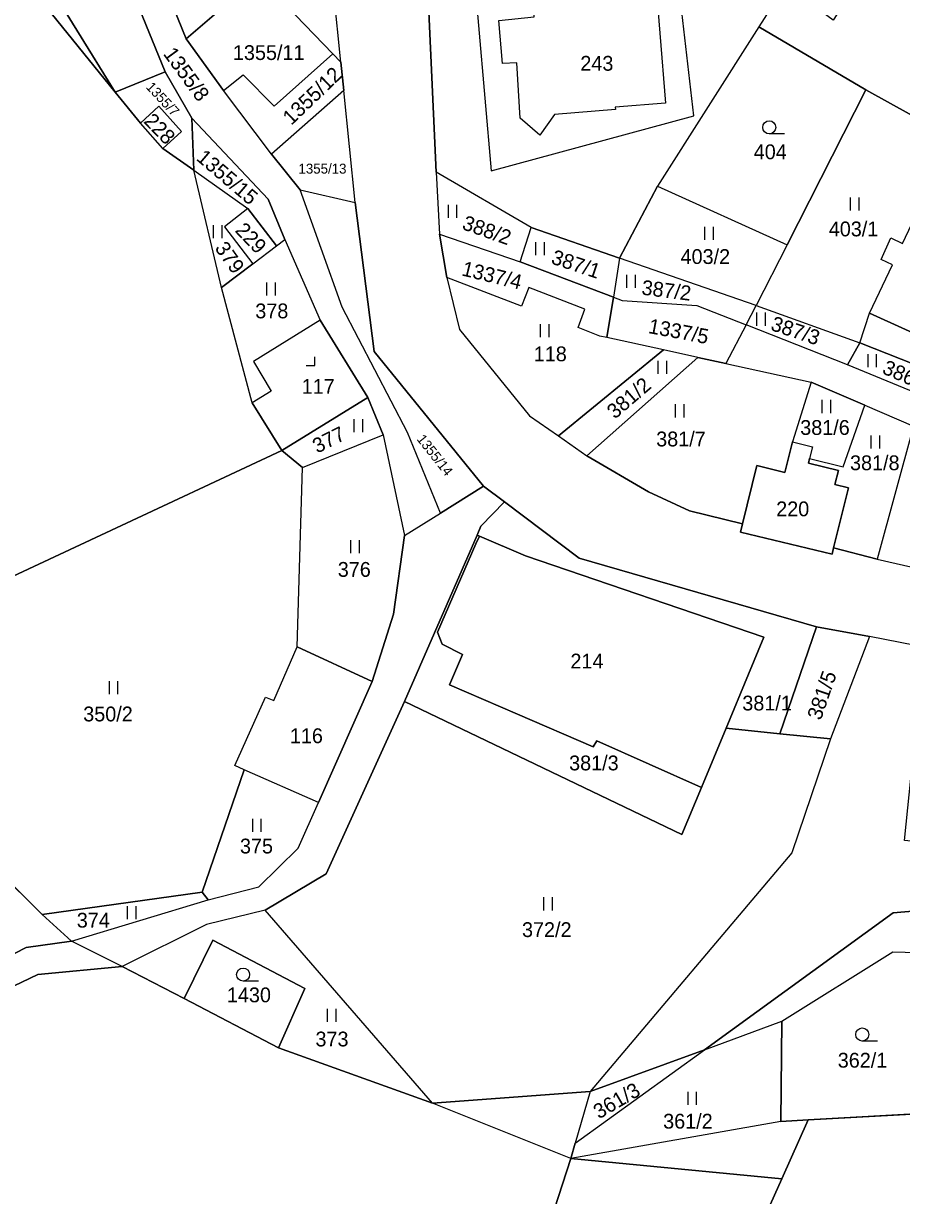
# Model space of a CAD drawing. Extents: x -588699 to -585793, y -1060280 to -1056731.
# Drawn here: x -587382.9 to -587282, y -1058613.5 to -1058478.9 of the extents above; entities that cross this region are included whole.
import ezdxf

# ---------------------------------------------------------------- set-up
doc = ezdxf.new("R2010")
doc.units = 0
for name, color, linetype in [('Druh pozemku', 7, 'Continuous'), ('Lesy', 7, 'Continuous'), ('Parcela nároku', 7, 'Continuous')]:
    doc.layers.add(name, color=color, linetype=linetype)

msp = doc.modelspace()

# ---------------------------------------------------------------- linework, layer by layer
at = {"layer": 'Druh pozemku'}
for p, q in [((-587295.46, -1058491.61), (-587297.21, -1058491.61)), ((-587287.9, -1058498.91), (-587287.9, -1058500.41)), ((-587286.88, -1058500.41), (-587286.88, -1058498.91)), ((-587334.09, -1058499.74), (-587334.09, -1058501.24)), ((-587333.07, -1058501.24), (-587333.07, -1058499.74)), ((-587361.05, -1058502.07), (-587361.05, -1058503.57)), ((-587360.03, -1058503.57), (-587360.03, -1058502.07)), ((-587304.64, -1058502.27), (-587304.64, -1058503.77)), ((-587303.61, -1058503.77), (-587303.61, -1058502.27)), ((-587324.04, -1058504.02), (-587324.04, -1058505.52)), ((-587323.02, -1058505.52), (-587323.02, -1058504.02)), ((-587354.93, -1058508.66), (-587354.93, -1058510.16)), ((-587353.91, -1058510.16), (-587353.91, -1058508.66)), ((-587313.61, -1058507.77), (-587313.61, -1058509.27)), ((-587312.58, -1058509.27), (-587312.58, -1058507.77)), ((-587298.67, -1058512.13), (-587298.67, -1058513.63)), ((-587297.65, -1058513.63), (-587297.65, -1058512.13)), ((-587323.5, -1058513.46), (-587323.5, -1058514.96)), ((-587322.47, -1058514.96), (-587322.47, -1058513.46)), ((-587310.01, -1058517.66), (-587310.01, -1058519.16)), ((-587308.98, -1058519.16), (-587308.98, -1058517.66)), ((-587285.9, -1058516.9), (-587285.9, -1058518.4)), ((-587284.88, -1058518.4), (-587284.88, -1058516.9)), ((-587291.15, -1058522.15), (-587291.15, -1058523.65)), ((-587290.12, -1058523.65), (-587290.12, -1058522.15)), ((-587308.02, -1058522.65), (-587308.02, -1058524.15)), ((-587306.99, -1058524.15), (-587306.99, -1058522.65)), ((-587344.9, -1058524.34), (-587344.9, -1058525.84)), ((-587343.88, -1058525.84), (-587343.88, -1058524.34)), ((-587285.53, -1058526.23), (-587285.53, -1058527.73)), ((-587284.51, -1058527.73), (-587284.51, -1058526.23)), ((-587345.3, -1058538.23), (-587345.3, -1058539.73)), ((-587344.28, -1058539.73), (-587344.28, -1058538.23)), ((-587373.03, -1058554.41), (-587373.03, -1058555.91)), ((-587372.01, -1058555.91), (-587372.01, -1058554.41)), ((-587356.56, -1058570.21), (-587356.56, -1058571.71)), ((-587355.54, -1058571.71), (-587355.54, -1058570.21)), ((-587323.12, -1058579.23), (-587323.12, -1058580.73)), ((-587322.09, -1058580.73), (-587322.09, -1058579.23)), ((-587370.94, -1058580.25), (-587370.94, -1058581.75)), ((-587369.92, -1058581.75), (-587369.92, -1058580.25)), ((-587355.88, -1058588.85), (-587357.63, -1058588.85)), ((-587347.96, -1058592.02), (-587347.96, -1058593.52)), ((-587346.94, -1058593.52), (-587346.94, -1058592.02)), ((-587284.77, -1058595.73), (-587286.52, -1058595.73)), ((-587306.57, -1058601.54), (-587306.57, -1058603.04)), ((-587305.55, -1058603.04), (-587305.55, -1058601.54))]:
    msp.add_line(p, q, dxfattribs=at)
msp.add_lwpolyline([(-587350.4, -1058518.2), (-587349.4, -1058518.2), (-587349.4, -1058517.2)], dxfattribs=at)
for centre in [(-587297.21, -1058490.86), (-587357.63, -1058588.1), (-587286.52, -1058594.98)]:
    msp.add_circle(centre, 0.75, dxfattribs=at)
at = {"layer": 'Lesy'}
for p, q in [((-587380.72, -1058581.19), (-587388.41, -1058573.59)), ((-587377.32, -1058584.26), (-587380.72, -1058581.19)), ((-587371.51, -1058587.16), (-587377.32, -1058584.26)), ((-587371.51, -1058587.16), (-587371.51, -1058587.16)), ((-587277.34, -1058603.93), (-587292.72, -1058604.78))]:
    msp.add_line(p, q, dxfattribs=at)
for points in [[(-587353.56, -1058596.5), (-587364.41, -1058590.86), (-587371.51, -1058587.16)], [(-587292.72, -1058604.78), (-587295.88, -1058604.95), (-587319.99, -1058609.19), (-587335.88, -1058602.84), (-587353.56, -1058596.5)]]:
    msp.add_lwpolyline(points, dxfattribs=at)
at = {"layer": 'Parcela nároku'}
for points in [[(-587366.84, -1058493.28), (-587369.43, -1058490.39), (-587372.32, -1058486.82), (-587383.27, -1058473.29), (-587387.17, -1058457.65), (-587399.19, -1058455.85), (-587399.62, -1058453.38), (-587401.07, -1058444.99), (-587390.46, -1058443.87), (-587391.11, -1058441.15), (-587404.22, -1058442.38), (-587420.9, -1058447.74), (-587445.16, -1058450.74), (-587438.44, -1058459.33), (-587434.17, -1058464.54), (-587411.26, -1058526.15), (-587394.79, -1058547.38), (-587353.18, -1058527.95), (-587356.59, -1058522.48), (-587360.11, -1058509.24), (-587363.28, -1058495.79)], [(-587387.17, -1058457.65), (-587383.27, -1058473.29), (-587372.32, -1058486.82), (-587381.11, -1058472.57), (-587381.9, -1058460.82), (-587385.63, -1058455.07), (-587388.15, -1058446.85), (-587387.94, -1058443.52), (-587387.62, -1058440.82), (-587391.11, -1058441.15), (-587390.46, -1058443.87), (-587387.83, -1058454.88)], [(-587328.68, -1058450.7), (-587295.33, -1058474.5), (-587298.4, -1058479.32), (-587310.04, -1058497.61), (-587314.4, -1058505.87), (-587324.56, -1058502.36), (-587335.45, -1058496.02), (-587336.43, -1058475.04), (-587339.12, -1058456.34), (-587340.81, -1058452.21), (-587340.72, -1058448.59)], [(-587359.3, -1058468.16), (-587364.35, -1058469.37), (-587368.7, -1058469.57), (-587364.16, -1058480.69), (-587355.85, -1058473.53)], [(-587353.49, -1058469.57), (-587359.3, -1058468.16), (-587355.85, -1058473.53), (-587347.32, -1058482.43), (-587346.4, -1058483.39), (-587347.22, -1058475.38)], [(-587372.91, -1058469.01), (-587381.11, -1058472.57), (-587372.32, -1058486.82), (-587366.59, -1058484.48)], [(-587368.7, -1058469.57), (-587371.87, -1058468.56), (-587372.91, -1058469.01), (-587366.59, -1058484.48), (-587363.52, -1058489.79), (-587354.76, -1058499.12), (-587352.83, -1058503.74), (-587348.78, -1058513), (-587343.3, -1058521.88), (-587341.53, -1058526.14), (-587339.1, -1058537.7), (-587334.98, -1058535.14), (-587338.75, -1058525.9), (-587346.27, -1058511.51), (-587351.06, -1058498.02), (-587354.38, -1058493.93), (-587359.88, -1058486.64), (-587364.16, -1058480.69)], [(-587329.16, -1058495.87), (-587305.86, -1058489.55), (-587308.29, -1058468.6), (-587331.33, -1058470.78)], [(-587305.86, -1058489.55), (-587308.29, -1058468.6), (-587331.33, -1058470.78), (-587329.16, -1058495.87)], [(-587324.32, -1058476.81), (-587316.39, -1058476.18), (-587316.63, -1058472.49), (-587310.44, -1058471.96), (-587309.12, -1058488.07), (-587314.9, -1058488.53), (-587314.88, -1058488.83), (-587321.85, -1058489.4), (-587323.55, -1058491.76), (-587325.8, -1058489.82), (-587326.21, -1058483.46), (-587327.84, -1058483.54), (-587328.27, -1058478.58), (-587324.21, -1058478.19), (-587324.18, -1058477.77)], [(-587325.8, -1058489.82), (-587326.21, -1058483.46), (-587327.84, -1058483.54), (-587328.27, -1058478.58), (-587324.21, -1058478.19), (-587324.18, -1058477.77), (-587324.32, -1058476.81), (-587316.39, -1058476.18), (-587316.63, -1058472.49), (-587310.44, -1058471.96), (-587309.12, -1058488.07), (-587314.9, -1058488.53), (-587314.88, -1058488.83), (-587321.85, -1058489.4), (-587323.55, -1058491.76)], [(-587355.85, -1058473.53), (-587364.16, -1058480.69), (-587359.88, -1058486.64), (-587357.64, -1058484.85), (-587354.06, -1058488.43), (-587347.32, -1058482.43)], [(-587289.85, -1058478.55), (-587295.33, -1058474.5), (-587298.4, -1058479.32), (-587286.1, -1058486.55), (-587270.51, -1058495.22), (-587266.46, -1058497.47), (-587260.05, -1058485.93), (-587259.1, -1058484.17), (-587285.98, -1058472.53)], [(-587286.1, -1058486.55), (-587298.4, -1058479.32), (-587310.04, -1058497.61), (-587295.16, -1058504.33)], [(-587357.64, -1058484.85), (-587354.06, -1058488.43), (-587347.32, -1058482.43), (-587346.4, -1058483.39), (-587346.07, -1058486.64), (-587354.38, -1058493.93), (-587359.88, -1058486.64)], [(-587366.84, -1058493.28), (-587363.28, -1058495.79), (-587363.52, -1058489.79), (-587366.59, -1058484.48), (-587372.32, -1058486.82), (-587369.43, -1058490.39), (-587367.31, -1058488.44), (-587364.69, -1058491.35)], [(-587344.77, -1058499.48), (-587346.07, -1058486.64), (-587354.38, -1058493.93), (-587351.06, -1058498.02)], [(-587283.06, -1058506.65), (-587284.34, -1058506.04), (-587283.23, -1058503.55), (-587281.9, -1058504.18), (-587278.65, -1058497.34), (-587273.07, -1058500.08), (-587270.51, -1058495.22), (-587286.1, -1058486.55), (-587295.16, -1058504.33), (-587298.72, -1058511.3), (-587286.8, -1058515.59), (-587285.69, -1058512.19)], [(-587364.69, -1058491.35), (-587366.84, -1058493.28), (-587369.43, -1058490.39), (-587367.31, -1058488.44)], [(-587354.76, -1058499.12), (-587363.52, -1058489.79), (-587363.28, -1058495.79), (-587357.07, -1058500.18), (-587353.79, -1058504.46), (-587352.83, -1058503.74)], [(-587273.07, -1058500.08), (-587270.51, -1058495.22), (-587266.46, -1058497.47), (-587275.65, -1058519.98), (-587286.8, -1058515.59), (-587285.69, -1058512.19), (-587277.01, -1058516.13), (-587272.75, -1058506.85), (-587275.76, -1058505.21)], [(-587359.75, -1058502.27), (-587356.52, -1058506.53), (-587360.11, -1058509.24), (-587363.28, -1058495.79), (-587357.07, -1058500.18)], [(-587324.56, -1058502.36), (-587335.45, -1058496.02), (-587335.09, -1058503.13), (-587325.8, -1058506.3)], [(-587314.4, -1058505.87), (-587310.04, -1058497.61), (-587295.16, -1058504.33), (-587298.72, -1058511.3)], [(-587285.69, -1058512.19), (-587283.06, -1058506.65), (-587284.34, -1058506.04), (-587283.23, -1058503.55), (-587281.9, -1058504.18), (-587278.65, -1058497.34), (-587273.07, -1058500.08), (-587275.76, -1058505.21), (-587272.75, -1058506.85), (-587277.01, -1058516.13)], [(-587351.06, -1058498.02), (-587344.77, -1058499.48), (-587342.59, -1058516.57), (-587330.02, -1058532.05), (-587334.98, -1058535.14), (-587338.75, -1058525.9), (-587346.27, -1058511.51)], [(-587357.07, -1058500.18), (-587359.75, -1058502.27), (-587356.52, -1058506.53), (-587353.79, -1058504.46)], [(-587335.09, -1058503.13), (-587325.8, -1058506.3), (-587315.11, -1058510.34), (-587315.85, -1058514.98), (-587316.66, -1058514.81), (-587319.17, -1058513.85), (-587318.37, -1058511.72), (-587324.83, -1058509.26), (-587325.66, -1058511.38), (-587334.24, -1058508.1)], [(-587325.8, -1058506.3), (-587324.56, -1058502.36), (-587314.4, -1058505.87), (-587315.11, -1058510.34)], [(-587356.59, -1058522.48), (-587360.11, -1058509.24), (-587356.52, -1058506.53), (-587353.79, -1058504.46), (-587352.83, -1058503.74), (-587348.78, -1058513), (-587356.43, -1058517.73), (-587354.39, -1058521.13)], [(-587314.4, -1058505.87), (-587315.11, -1058510.34), (-587314.08, -1058510.73), (-587305.51, -1058511.32), (-587299.85, -1058513.54), (-587298.72, -1058511.3)], [(-587325.66, -1058511.38), (-587334.24, -1058508.1), (-587332.76, -1058514.08), (-587324.74, -1058523.98), (-587321.42, -1058526.28), (-587309.35, -1058516.41), (-587315.85, -1058514.98), (-587316.66, -1058514.81), (-587319.17, -1058513.85), (-587318.37, -1058511.72), (-587324.83, -1058509.26)], [(-587315.85, -1058514.98), (-587315.11, -1058510.34), (-587314.08, -1058510.73), (-587305.51, -1058511.32), (-587299.85, -1058513.54), (-587302.18, -1058517.98), (-587305.41, -1058517.27), (-587309.35, -1058516.41)], [(-587298.72, -1058511.3), (-587286.8, -1058515.59), (-587288.21, -1058518.12), (-587299.85, -1058513.54)], [(-587343.3, -1058521.88), (-587348.78, -1058513), (-587356.43, -1058517.73), (-587354.39, -1058521.13), (-587356.59, -1058522.48), (-587353.18, -1058527.95)], [(-587279.12, -1058521.86), (-587288.21, -1058518.12), (-587299.85, -1058513.54), (-587302.18, -1058517.98), (-587292.41, -1058520.12), (-587286.22, -1058522.76), (-587280.63, -1058525.14), (-587273.26, -1058527.98), (-587254.61, -1058535.18), (-587249.04, -1058540.61), (-587230.94, -1058549.73), (-587219.46, -1058550.78), (-587233.82, -1058545.1), (-587237.26, -1058543.38), (-587245.92, -1058538.86), (-587250.73, -1058534.66), (-587259.7, -1058530.08), (-587271.77, -1058524.3)], [(-587305.41, -1058517.27), (-587309.35, -1058516.41), (-587321.42, -1058526.28), (-587318.14, -1058528.56)], [(-587288.21, -1058518.12), (-587286.8, -1058515.59), (-587275.65, -1058519.98), (-587276.21, -1058521), (-587279.12, -1058521.86)], [(-587302.18, -1058517.98), (-587292.41, -1058520.12), (-587294.54, -1058526.95), (-587294.99, -1058528.81), (-587295.4, -1058530.47), (-587298.63, -1058529.67), (-587300.27, -1058536.36), (-587306.35, -1058534.87), (-587311.06, -1058532.7), (-587318.14, -1058528.56), (-587305.41, -1058517.27)], [(-587292.41, -1058520.12), (-587294.54, -1058526.95), (-587292.24, -1058527.52), (-587292.57, -1058528.86), (-587288.71, -1058529.81), (-587286.22, -1058522.76)], [(-587388.41, -1058573.59), (-587380.72, -1058581.19), (-587377.32, -1058584.26), (-587382.53, -1058584.99), (-587391.56, -1058589.63), (-587398.31, -1058607.56), (-587418.55, -1058619.21), (-587421.42, -1058614.02), (-587424.8, -1058613.98), (-587442.12, -1058596.89), (-587453.48, -1058608.36), (-587483.06, -1058578.42), (-587446.36, -1058525.22), (-587444.96, -1058522.12), (-587408.96, -1058549.02), (-587404.2, -1058551.85), (-587403.36, -1058552.35), (-587385.5, -1058562.34)], [(-587341.53, -1058526.14), (-587343.3, -1058521.88), (-587353.18, -1058527.95), (-587350.82, -1058529.89)], [(-587289.66, -1058531.86), (-587289.26, -1058530.24), (-587292.7, -1058529.4), (-587292.57, -1058528.86), (-587288.71, -1058529.81), (-587286.22, -1058522.76), (-587280.63, -1058525.14), (-587284.8, -1058540.42), (-587289.81, -1058539.11), (-587288.11, -1058532.24)], [(-587350.82, -1058529.89), (-587341.53, -1058526.14), (-587339.1, -1058537.7), (-587340.35, -1058546.72), (-587342.82, -1058554.47), (-587351.41, -1058550.47)], [(-587273.26, -1058527.98), (-587280.63, -1058525.14), (-587284.8, -1058540.42), (-587270.53, -1058543.69), (-587257.43, -1058545.14), (-587276.9, -1058538.54)], [(-587300.27, -1058536.36), (-587298.63, -1058529.67), (-587295.4, -1058530.47), (-587294.99, -1058528.81), (-587294.54, -1058526.95), (-587292.24, -1058527.52), (-587292.57, -1058528.86), (-587292.7, -1058529.4), (-587289.26, -1058530.24), (-587289.66, -1058531.86), (-587288.11, -1058532.24), (-587289.81, -1058539.11), (-587289.99, -1058539.83), (-587300.51, -1058537.32)], [(-587385.5, -1058562.34), (-587388.41, -1058573.59), (-587380.72, -1058581.19), (-587362.35, -1058578.65), (-587357.49, -1058564.59), (-587358.57, -1058564.12), (-587355.07, -1058556.25), (-587354.12, -1058556.65), (-587351.41, -1058550.47), (-587350.82, -1058529.89), (-587353.18, -1058527.95), (-587394.79, -1058547.38), (-587403.36, -1058552.35)], [(-587299.58, -1058553.63), (-587297.83, -1058549.37), (-587325.2, -1058540.03), (-587330.5, -1058537.78), (-587330.76, -1058537.67), (-587330.32, -1058536.65), (-587327.61, -1058533.86), (-587319.05, -1058540.32), (-587291.79, -1058548.2), (-587295.99, -1058560.45), (-587302.17, -1058559.83)], [(-587333.93, -1058554.84), (-587326.13, -1058558.22), (-587317.44, -1058561.96), (-587317, -1058561.28), (-587305, -1058566.61), (-587307.26, -1058572.02), (-587339.08, -1058556.76), (-587330.76, -1058537.67), (-587330.5, -1058537.78), (-587330.89, -1058538.67), (-587335.29, -1058548.81), (-587334.76, -1058550.16), (-587332.43, -1058551.36)], [(-587330.89, -1058538.67), (-587330.5, -1058537.78), (-587325.2, -1058540.03), (-587297.83, -1058549.37), (-587299.58, -1058553.63), (-587302.17, -1058559.83), (-587305, -1058566.61), (-587317, -1058561.28), (-587317.44, -1058561.96), (-587326.13, -1058558.22), (-587333.93, -1058554.84), (-587332.43, -1058551.36), (-587334.76, -1058550.16), (-587335.29, -1058548.81)], [(-587295.99, -1058560.45), (-587291.79, -1058548.2), (-587285.68, -1058549.28), (-587290.17, -1058561.03)], [(-587294.63, -1058574.11), (-587317.78, -1058601.52), (-587304.66, -1058596.72), (-587282.96, -1058581.02), (-587254.46, -1058578.55), (-587220.71, -1058579.64), (-587220.7, -1058576.24), (-587222.71, -1058566.21), (-587240.09, -1058564.87), (-587246.73, -1058564.36), (-587250.92, -1058567.18), (-587251.85, -1058575.82), (-587281.68, -1058572.72), (-587279.66, -1058552.85), (-587262.25, -1058554.64), (-587261.44, -1058554.03), (-587285.68, -1058549.28), (-587290.17, -1058561.03)], [(-587354.12, -1058556.65), (-587351.41, -1058550.47), (-587342.82, -1058554.47), (-587348.98, -1058568.34), (-587357.49, -1058564.59), (-587358.57, -1058564.12), (-587355.07, -1058556.25)], [(-587355.09, -1058580.71), (-587348.08, -1058576.53), (-587339.08, -1058556.76), (-587307.26, -1058572.02), (-587305, -1058566.61), (-587302.17, -1058559.83), (-587295.99, -1058560.45), (-587290.17, -1058561.03), (-587294.63, -1058574.11), (-587317.78, -1058601.52), (-587335.88, -1058602.84)], [(-587348.98, -1058568.34), (-587357.49, -1058564.59), (-587362.35, -1058578.65), (-587361.63, -1058579.52), (-587355.82, -1058578.04), (-587351.31, -1058573.58)], [(-587361.63, -1058579.52), (-587362.35, -1058578.65), (-587380.72, -1058581.19), (-587377.32, -1058584.26)], [(-587254.46, -1058578.55), (-587282.96, -1058581.02), (-587304.66, -1058596.72), (-587295.76, -1058593.46), (-587283.01, -1058585.47), (-587260.29, -1058586.12), (-587222.76, -1058580.99), (-587220.99, -1058594.48), (-587220.71, -1058579.64)], [(-587335.88, -1058602.84), (-587355.09, -1058580.71), (-587361.85, -1058582.35), (-587371.51, -1058587.16), (-587364.41, -1058590.86), (-587361.11, -1058584.15), (-587350.55, -1058589.69), (-587353.56, -1058596.5)], [(-587350.55, -1058589.69), (-587361.11, -1058584.15), (-587364.41, -1058590.86), (-587353.56, -1058596.5)], [(-587295.76, -1058593.46), (-587283.01, -1058585.47), (-587260.29, -1058586.12), (-587278.12, -1058588.15), (-587277.34, -1058603.93), (-587292.72, -1058604.78), (-587295.88, -1058604.95)], [(-587408.99, -1058618.31), (-587395.9, -1058610.54), (-587388.51, -1058591.59), (-587381.21, -1058588.08), (-587371.51, -1058587.16), (-587364.41, -1058590.86), (-587353.56, -1058596.5), (-587335.88, -1058602.84), (-587317.78, -1058601.52), (-587319.49, -1058607.45), (-587319.99, -1058609.19), (-587325.69, -1058626.76), (-587343.9, -1058658.93), (-587359, -1058685.62), (-587389.18, -1058667.68), (-587404.15, -1058652.71), (-587410.38, -1058646.84), (-587420.19, -1058649.19), (-587423.53, -1058636.88), (-587423.53, -1058626.81)], [(-587304.66, -1058596.72), (-587295.76, -1058593.46), (-587295.88, -1058604.95), (-587292.72, -1058604.78), (-587295.76, -1058611.54), (-587319.99, -1058609.19), (-587319.49, -1058607.45)], [(-587304.66, -1058596.72), (-587317.78, -1058601.52), (-587319.49, -1058607.45)], [(-587224.24, -1058611.38), (-587227.33, -1058622.64), (-587234.78, -1058641.05), (-587228.22, -1058654.57), (-587229.04, -1058654.03), (-587234.85, -1058650.19), (-587241.93, -1058647.92), (-587241.43, -1058646.05), (-587253.49, -1058642.78), (-587263.88, -1058656.92), (-587266.76, -1058656.19), (-587271.11, -1058674.46), (-587279.67, -1058672.58), (-587285.95, -1058680.73), (-587343.9, -1058658.93), (-587325.69, -1058626.76), (-587304.87, -1058631.83), (-587295.76, -1058611.54), (-587292.72, -1058604.78), (-587277.34, -1058603.93), (-587260.93, -1058603.03)], [(-587319.99, -1058609.19), (-587295.76, -1058611.54), (-587304.87, -1058631.83), (-587325.69, -1058626.76)]]:
    msp.add_lwpolyline(points, close=True, dxfattribs=at)
for points in [[(-587197.27, -1058559.81), (-587224.85, -1058557.57), (-587228.38, -1058557.34), (-587239.8, -1058556.34), (-587246.25, -1058555.77), (-587261.44, -1058554.03), (-587285.68, -1058549.28), (-587291.79, -1058548.2), (-587319.05, -1058540.32), (-587327.61, -1058533.86), (-587330.02, -1058532.05), (-587342.59, -1058516.57), (-587344.77, -1058499.48), (-587346.07, -1058486.64), (-587346.4, -1058483.39), (-587347.22, -1058475.38), (-587353.49, -1058469.57), (-587359.3, -1058468.16), (-587364.35, -1058469.37), (-587368.7, -1058469.57), (-587371.87, -1058468.56), (-587377.76, -1058465.86), (-587381.9, -1058460.82), (-587385.63, -1058455.07)], [(-587336.43, -1058475.04), (-587335.45, -1058496.02), (-587335.09, -1058503.13), (-587334.24, -1058508.1), (-587332.76, -1058514.08), (-587324.74, -1058523.98), (-587321.42, -1058526.28), (-587318.14, -1058528.56), (-587311.06, -1058532.7), (-587306.35, -1058534.87), (-587300.27, -1058536.36), (-587300.51, -1058537.32), (-587289.99, -1058539.83), (-587289.81, -1058539.11), (-587284.8, -1058540.42), (-587270.53, -1058543.69), (-587257.43, -1058545.14), (-587250.99, -1058546.1), (-587230.94, -1058549.73), (-587219.46, -1058550.78), (-587213.45, -1058550.88)], [(-587391.56, -1058589.63), (-587382.53, -1058584.99), (-587377.32, -1058584.26), (-587361.63, -1058579.52), (-587355.82, -1058578.04), (-587351.31, -1058573.58), (-587348.98, -1058568.34), (-587342.82, -1058554.47), (-587340.35, -1058546.72), (-587339.1, -1058537.7), (-587334.98, -1058535.14), (-587330.02, -1058532.05), (-587327.61, -1058533.86), (-587330.32, -1058536.65), (-587330.76, -1058537.67), (-587339.08, -1058556.76), (-587348.08, -1058576.53), (-587355.09, -1058580.71), (-587361.85, -1058582.35), (-587371.51, -1058587.16), (-587381.21, -1058588.08), (-587388.51, -1058591.59)]]:
    msp.add_lwpolyline(points, dxfattribs=at)

# ---------------------------------------------------------------- texts
for s, height, rotation, p in [('1355/8', 1.7, 306.2408, (-587366.87, -1058482.44)), ('1355/12', 1.7, 43.8542, (-587352.09, -1058490.69)), ('1355/7', 1.14, 312.9447, (-587368.86, -1058486.29)), ('228', 1.7, 314.2934, (-587369.14, -1058490.25)), ('1355/15', 1.7, 319.4892, (-587363.11, -1058494.54)), ('229', 1.7, 313.7711, (-587358.65, -1058502.77)), ('388/2', 1.7, 340.4944, (-587332.59, -1058502.51)), ('379', 1.7, 305.3382, (-587360.95, -1058504.73)), ('387/1', 1.7, 341.5531, (-587322.36, -1058506.46)), ('1337/4', 1.7, 346.2917, (-587332.62, -1058507.84)), ('387/2', 1.7, 352.7456, (-587311.94, -1058510.05)), ('387/3', 1.7, 341.6387, (-587297.15, -1058514.1)), ('1337/5', 1.7, 349.3802, (-587311.18, -1058514.46)), ('386/1', 1.7, 336.6063, (-587284.35, -1058519.05)), ('381/2', 1.7, 40.6384, (-587314.94, -1058524.41)), ('377', 1.7, 26.5634, (-587349.12, -1058528.32)), ('1355/14', 1.14, 308.2227, (-587337.75, -1058526.66)), ('381/5', 1.7, 70.9814, (-587291.29, -1058559)), ('361/3', 1.7, 30.221, (-587316.77, -1058604.73))]:
    msp.add_text(s, height=height, rotation=rotation, dxfattribs=at).set_placement(p)
for s, height, p in [('1355/11', 1.7, (-587358.8, -1058483.13)), ('243', 1.7, (-587318.9, -1058484.36)), ('404', 1.7, (-587298.99, -1058494.52)), ('1355/13', 1.14, (-587351.27, -1058496.17)), ('403/1', 1.7, (-587290.37, -1058503.37)), ('403/2', 1.7, (-587307.39, -1058506.54)), ('378', 1.7, (-587356.23, -1058512.78)), ('118', 1.7, (-587324.25, -1058517.71)), ('117', 1.7, (-587350.9, -1058521.44)), ('381/6', 1.7, (-587293.65, -1058526.16)), ('381/7', 1.7, (-587310.19, -1058527.48)), ('381/8', 1.7, (-587287.93, -1058530.21)), ('220', 1.7, (-587296.41, -1058535.5)), ('376', 1.7, (-587346.76, -1058542.45)), ('214', 1.7, (-587320.04, -1058552.97)), ('381/1', 1.7, (-587300.3, -1058557.79)), ('350/2', 1.7, (-587375.99, -1058559.04)), ('116', 1.7, (-587352.26, -1058561.54)), ('381/3', 1.7, (-587320.19, -1058564.66)), ('375', 1.7, (-587357.99, -1058574.2)), ('374', 1.7, (-587376.73, -1058582.71)), ('372/2', 1.7, (-587325.6, -1058583.79)), ('1430', 1.7, (-587359.49, -1058591.28)), ('373', 1.7, (-587349.32, -1058596.35)), ('362/1', 1.7, (-587289.34, -1058598.78)), ('361/2', 1.7, (-587309.39, -1058605.78))]:
    msp.add_text(s, height=height, dxfattribs=at).set_placement(p)

doc.saveas('drawing.dxf')
